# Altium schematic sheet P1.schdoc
size 297 x 209 mm; Symbol: Drawing-Symbol_A4; @Project Name: Td5 OBD2; @Page Count: 1; @Update Date: 2025-10-22; @Create Date: 2025-10-22; @Schematic Name: Schematic1; @Page No: 1; @Page Name: P1; Company: EasyEDA.com; Version: V1.0; Page Size: A4; @Create Time: 10:26:54; @Update Time: 11:26:54; Border: 1; Width: 1170; Height: 825; Region Start: 1; X Region Count: 6; Y Region Count: 4; Blade Width: 10; Title Block Position: 3; @Board Name: Board1; Device: Drawing-Symbol_A4
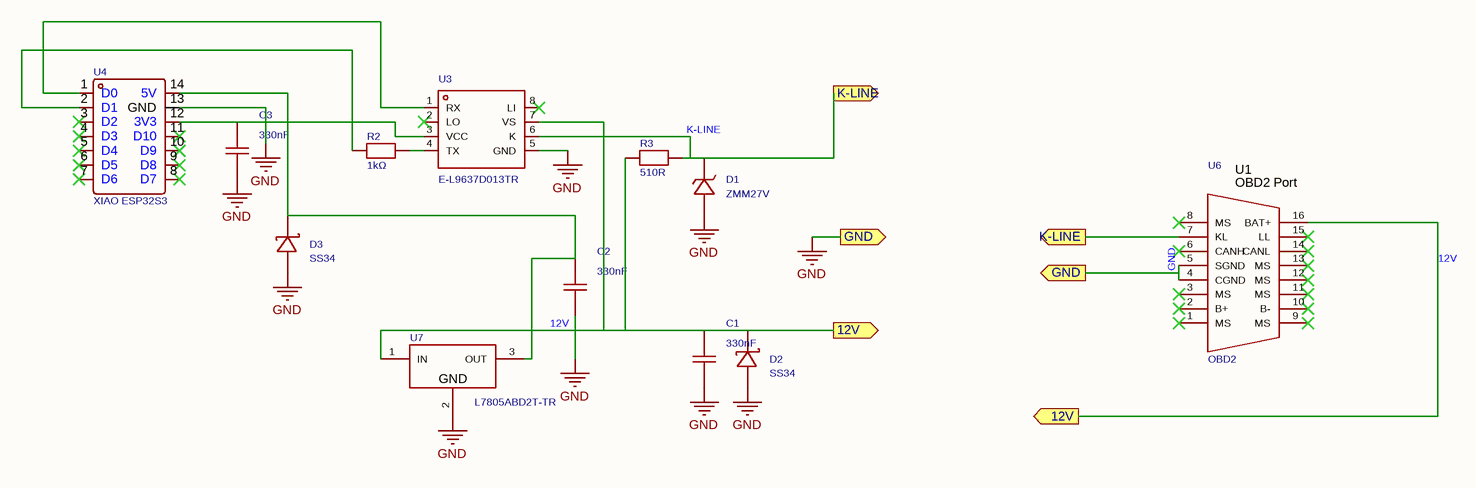
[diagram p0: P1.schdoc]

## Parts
C1  330nF  [C0603]
C2  330nF  [C0603]
C3  330nF  [C0603]
D1  ZMM27V  [LL-34_L3.5-W1.5-RD]
D2  SS34  [SMA_L4.3-W2.6-LS5.2-RD]
D3  SS34  [SMA_L4.3-W2.6-LS5.2-RD]
R2  1kΩ  [R0603]
R3  510R  [R0603]
U3  E-L9637D013TR  [SOIC-8_L4.9-W3.9-P1.27-LS6.0-BL]
U4  XIAO ESP32S3  [COMM-SMD_KQ-2801_V106]
U6  OBD2  [OBD2]
U7  L7805ABD2T-TR  [TO-263-2_L10.0-W9.2-P5.08-LS15.3-TL-CW]

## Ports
12V (out), GND (out), K-LINE (out)

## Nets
GND: C1.1 C2.1 C3.1 D1.2(A) D2.2(A) D3.2(A) U3.5(GND) U4.13(GND) U6.4(CGND) U6.5(SGND) U7.2(GND) ; port GND
12V: C1.2 D2.1(K) R3.1 U3.7(VS) U6.16(BAT+) U7.1(IN) ; port 12V
K-LINE: D1.1(C) R3.2 U3.6(K) U6.7(KL) ; port K-LINE
NetC2_2: C2.2 D3.1(K) U4.14(5V) U7.3(OUT)
NetC3_2: C3.2 U3.3(VCC) U4.12(3V3)
NetR2_1: R2.1 U4.2(D1)
NetR2_2: R2.2 U3.4(TX)
NetU3_1: U3.1(RX) U4.1(D0)

Not connected (* = marked no-connect by the designer): U3 2(LO)* 8(LI)*; U4 3(D2)* 4(D3)* 5(D4)* 6(D5)* 7(D6)* 8(D7)* 9(D8)* 10(D9)* 11(D10)*; U6 1(MS)* 2(B+)* 3(MS)* 6(CANH)* 8(MS)* 9(MS)* 10(B-)* 11(MS)* 12(MS)* 13(MS)* 14(CANL)* 15(LL)*

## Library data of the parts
C1-C3 = TCC0603X7R334K500CT: Capacitance:330nF Tolerance:±10% Tolerance:±10% Voltage Rating:50V Temperature Coefficient:X7R; Manufacturer: CCTC(三环); AddInBom: yes; ModelId: 624118aa3cc7497086c383c2d72e0852; ModelName: C0603_L1.6-W0.8-H0.8; ModelTransform: 62.992,31.496,0,0,0,0,0,0,0; Tolerance: ±10%; Voltage Rating: 50V; Temperature Coefficient: X7R
D1 = ZMM27V: Diode Configuration:Independent Zener Voltage(Nom):27V Reverse Leakage Current (Ir):100nA@20V Zener Voltage(Range):25.1V~28.9V Zener Voltage(Range):25.1V~28.9V Pd - Power Dissipation:500mW Impedance(Zzt):80Ω; Manufacturer: JSMSEMI(杰盛微); AddInBom: yes; ModelId: 501a94dacdf743d08e001ac7609ed22e; ModelName: LL-34_L3.5-W1.5; ModelTransform: 133.93674,59.031,0,0,0,0,0,0,0; Zener Voltage(Nom): 27V; Pd - Power Dissipation: 500mW; Impedance(Zzt): 80Ω
D2 D3 = SS34_C8678: Diode Configuration:Independent Voltage - Forward(Vf@If):550mV@3A Voltage - DC Reverse(Vr):40V Current - Rectified:3A Reverse Leakage Current (Ir):500uA@40V Operating Junction Temperature Range:-55℃~+125℃ Operating Junction Temperature Range:-55℃~+125℃; Manufacturer: MDD(辰达半导体); AddInBom: yes; ModelId: e3551acb3c5a4975a5e9d36087fe1fa2; ModelTransform: 185.039,102.362,0,0,0,0,0,0,0; Voltage - DC Reverse(Vr): 40V; Current - Rectified: 3A
R2 = FRC0603F1001TS: Type:Thick Film Resistor Resistance:1kΩ Tolerance:±1% Tolerance:±1% Power(Watts):100mW Voltage-Supply(Max):75V Temperature Coefficient:±100ppm/℃ Temperature Coefficient:±100ppm/℃ Operating Temperature:-55℃~+155℃ Operating Temperature:-55℃~+155℃; Manufacturer: FOJAN(富捷); AddInBom: yes; ModelId: 112863783b5b41f1b5254f87eedc7932; ModelTransform: 31.8897,63.7794,0,90,0,0,0,0,0; Tolerance: ±1%; Power(Watts): 100mW; Voltage-Supply(Max): 75V
R3 = 510R: AddInBom: yes
U3 = E-L9637D013TR: Data Rate:50Kbps Voltage - Supply:4.5V~36V Voltage - Supply:4.5V~36V Operating Temperature:-40℃~+150℃ Operating Temperature:-40℃~+150℃; Manufacturer: ST(意法半导体); AddInBom: yes; ModelId: 2ec1ac1bf9bf4d09a988fcee15e6a02d; ModelName: SOIC-8_L4.9-W3.9-H1.7-LS6.0-P1.27; ModelTransform: 189.751,236.22,0,0,0,0,0.0005,0.0005,0; Data Rate: 50Kbps
U4 = XIAO ESP32S3: Manufacturer: null; ManufacturerPart: XIAO ESP32C3; ConvertToPcb: yes
U6 = OBD2: AddInBom: yes
U7 = L7805ABD2T-TR: Output Type:Fixed Maximum Input Voltage:35V Output Voltage:5V Output Voltage:5V Output Current:1.5A Power Supply Rejection Ratio (PSRR):68dB@(120Hz) Dropout Voltage:2V@(1A) standby current:6mA Feature:Short-Circuit  Protection；Thermal Protection(TSD) Oper; Manufacturer: ST(意法半导体); AddInBom: yes; ModelId: 8bcb4b56af2a4890b93c56daf9f63a80; ModelName: TO-263-2_L10.2-W8.7-H4.5-LS15.2-P2.54; ModelTransform: 401.574,591.64307,0,270,0,0,54.134,0.079,0; Output Type: Fixed; Maximum Input Voltage: 35V; Output Voltage: 5V; Output Current: 1.5A; standby current: 6mA; Output Polarity: Positive electrode; Number of Outputs: 1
